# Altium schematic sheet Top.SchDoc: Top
size A4; Date: Not used; ApprovedBy: Not used; CheckedBy: Not used; Author: Not used; CompanyName: STMicroelectronics; DrawnBy: Not used; Engineer: Not used; Organization: Not used; Address1: Not used; Address2: Not used; Address3: Not used; Address4: Not used; DocumentNumber: 2; Revision: A-01-P3; SheetNumber: 2; SheetTotal: 8
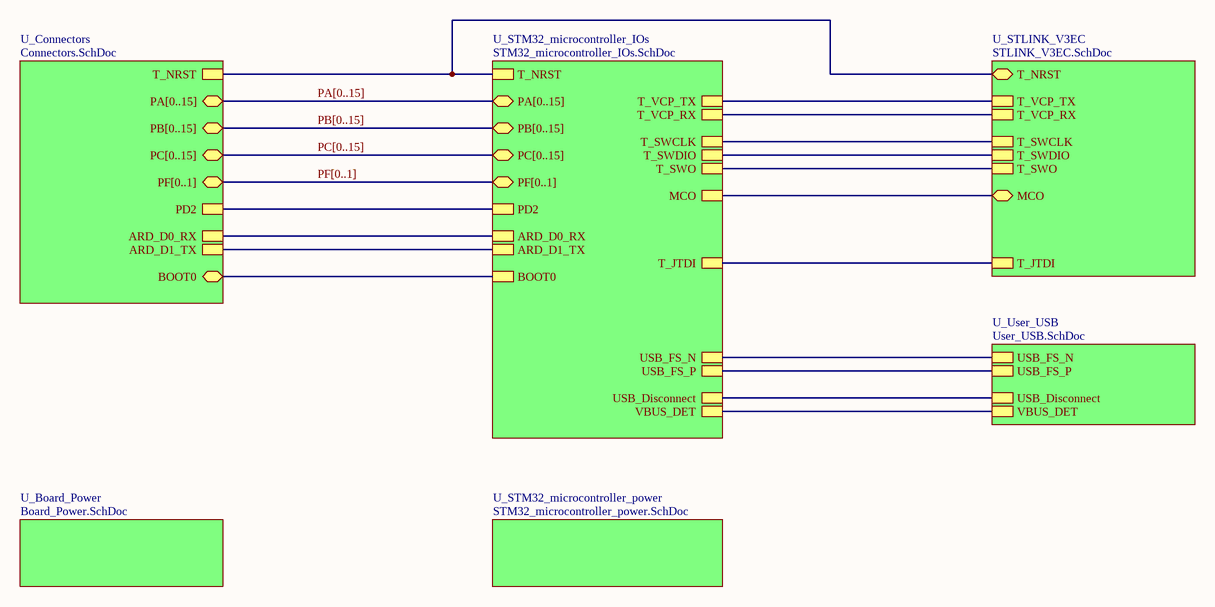
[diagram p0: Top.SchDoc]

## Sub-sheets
U_Board_Power = Board_Power.SchDoc: no entries
U_Connectors = Connectors.SchDoc: PA[0..15] (bidir), PB[0..15] (bidir), PC[0..15] (bidir), PD2, T_NRST, PF[0..1] (bidir), ARD_D0_RX, ARD_D1_TX, BOOT0 (bidir)
U_STLINK_V3EC = STLINK_V3EC.SchDoc: T_NRST (bidir), MCO (bidir), T_VCP_RX, T_VCP_TX, T_JTDI, T_SWCLK, T_SWO, T_SWDIO
U_STM32_microcontroller_IOs = STM32_microcontroller_IOs.SchDoc: PA[0..15] (bidir), PB[0..15] (bidir), PC[0..15] (bidir), PF[0..1] (bidir), ARD_D0_RX, ARD_D1_TX, MCO, PD2, T_NRST, T_VCP_TX, T_VCP_RX, T_SWCLK, T_SWO, T_SWDIO, T_JTDI, USB_FS_N, USB_FS_P, BOOT0, USB_Disconnect, VBUS_DET
U_STM32_microcontroller_power = STM32_microcontroller_power.SchDoc: no entries
U_User_USB = User_USB.SchDoc: VBUS_DET, USB_FS_N, USB_FS_P, USB_Disconnect

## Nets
(unnamed): sheet U_STM32_microcontroller_IOs/ARD_D0_RX, sheet U_Connectors/ARD_D0_RX
(unnamed): sheet U_STM32_microcontroller_IOs/ARD_D1_TX, sheet U_Connectors/ARD_D1_TX  [a separate net that carries the same name]
(unnamed): sheet U_STM32_microcontroller_IOs/MCO, sheet U_STLINK_V3EC/MCO  [a separate net that carries the same name]
(unnamed): sheet U_STM32_microcontroller_IOs/PD2, sheet U_Connectors/PD2  [a separate net that carries the same name]
(unnamed): sheet U_STM32_microcontroller_IOs/T_NRST, sheet U_Connectors/T_NRST, sheet U_STLINK_V3EC/T_NRST  [a separate net that carries the same name]
(unnamed): sheet U_STM32_microcontroller_IOs/T_VCP_TX, sheet U_STLINK_V3EC/T_VCP_TX  [a separate net that carries the same name]
(unnamed): sheet U_STM32_microcontroller_IOs/T_VCP_RX, sheet U_STLINK_V3EC/T_VCP_RX  [a separate net that carries the same name]
(unnamed): sheet U_STM32_microcontroller_IOs/T_SWCLK, sheet U_STLINK_V3EC/T_SWCLK  [a separate net that carries the same name]
(unnamed): sheet U_STM32_microcontroller_IOs/T_SWO, sheet U_STLINK_V3EC/T_SWO  [a separate net that carries the same name]
(unnamed): sheet U_STM32_microcontroller_IOs/T_SWDIO, sheet U_STLINK_V3EC/T_SWDIO  [a separate net that carries the same name]
(unnamed): sheet U_STM32_microcontroller_IOs/T_JTDI, sheet U_STLINK_V3EC/T_JTDI  [a separate net that carries the same name]
(unnamed): sheet U_STM32_microcontroller_IOs/USB_FS_N, sheet U_User_USB/USB_FS_N  [a separate net that carries the same name]
(unnamed): sheet U_STM32_microcontroller_IOs/USB_FS_P, sheet U_User_USB/USB_FS_P  [a separate net that carries the same name]
(unnamed): sheet U_STM32_microcontroller_IOs/BOOT0, sheet U_Connectors/BOOT0  [a separate net that carries the same name]
(unnamed): sheet U_STM32_microcontroller_IOs/USB_Disconnect, sheet U_User_USB/USB_Disconnect  [a separate net that carries the same name]
(unnamed): sheet U_STM32_microcontroller_IOs/VBUS_DET, sheet U_User_USB/VBUS_DET  [a separate net that carries the same name]

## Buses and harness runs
bus PA[0..15] = sheet U_Connectors/PA[0..15] = sheet U_STM32_microcontroller_IOs/PA[0..15]
bus PB[0..15] = sheet U_Connectors/PB[0..15] = sheet U_STM32_microcontroller_IOs/PB[0..15]
bus PC[0..15] = sheet U_Connectors/PC[0..15] = sheet U_STM32_microcontroller_IOs/PC[0..15]
bus PF[0..1] = sheet U_Connectors/PF[0..1] = sheet U_STM32_microcontroller_IOs/PF[0..1]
